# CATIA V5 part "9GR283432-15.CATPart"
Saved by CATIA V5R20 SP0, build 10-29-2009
Part number: 9GR283432-15
Revision: ANY
Definition: UNKNOWN
Nomenclature: 9GR283432-15
Source: Unknown
Bounding box of the stored display mesh (mm): x -15.967 to 16, y -29 to 5, z -16 to 16
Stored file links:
  C:\Users\Utente\Desktop\IO LAVORO\3D X SITO CF\CUMSA\3D files GR\GR 283432-15\9GR283432-15.CATPart
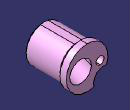
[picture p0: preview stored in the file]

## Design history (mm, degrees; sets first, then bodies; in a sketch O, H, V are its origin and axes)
Body1 "Cortar-Extruir7" (main body)
  Solid1: solid without history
